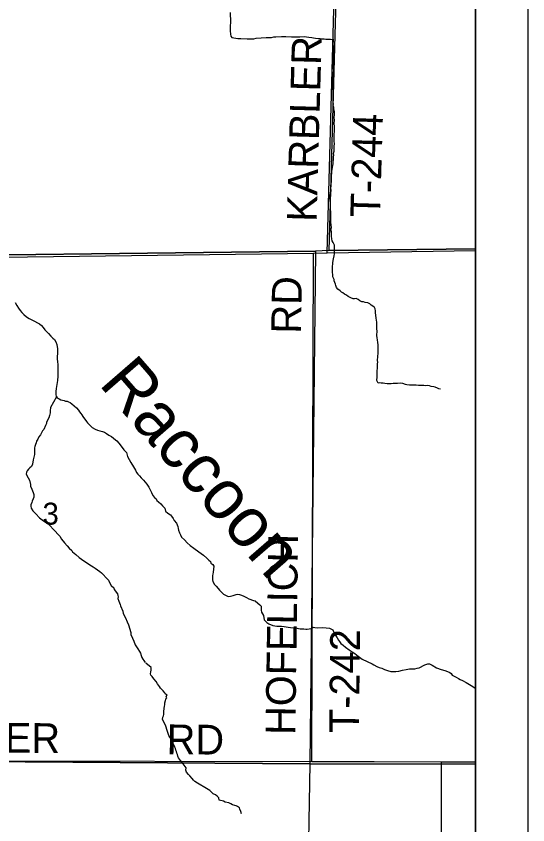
# Model space of a CAD drawing. Extents: x 0 to 34, y 0 to 22.
# Drawn here: x 29.44 to 30.417, y 18.79 to 20.335 of the extents above; entities that cross this region are included whole.
import ezdxf

# ---------------------------------------------------------------- set-up
doc = ezdxf.new("R2010")
doc.units = 0
for name, color, linetype in [('GM_X_County_Road', 7, 'Continuous'), ('GM_X_Minor_River', 7, 'Continuous'), ('GM_X_Minor_River_Text', 7, 'Continuous'), ('GM_X_Section', 7, 'Continuous'), ('GM_X_Section_Text', 7, 'Continuous'), ('GM_X_Township_Road', 7, 'Continuous'), ('GM_X_Township_Road_Text', 7, 'Continuous'), ('SH_Data', 7, 'Continuous')]:
    doc.layers.add(name, color=color, linetype=linetype)

msp = doc.modelspace()

# ---------------------------------------------------------------- linework, layer by layer
at = {"layer": 'GM_X_County_Road'}
msp.add_line((30.0335, 19.8831), (30.3167, 19.8876), dxfattribs=at)
msp.add_lwpolyline([(29.2621, 19.8726), (30.0076, 19.8826), (30.0335, 19.8831)], dxfattribs=at)
at = {"layer": 'GM_X_Minor_River'}
for points in [[(29.8485, 20.3425), (29.8486, 20.3235), (29.8482, 20.3163), (29.8483, 20.3072), (29.8491, 20.3007), (29.8494, 20.2973), (29.8517, 20.2946), (29.8631, 20.2924), (29.8688, 20.2925), (29.881, 20.2921), (29.8935, 20.2922), (29.8981, 20.2934), (29.9167, 20.2946), (29.922, 20.2942), (29.9273, 20.2943), (29.9318, 20.2954), (29.9356, 20.2958), (29.9466, 20.2962), (29.95, 20.2966), (29.9546, 20.2963), (29.9652, 20.2956), (29.9816, 20.2957), (29.9899, 20.2961), (29.9941, 20.2957), (29.9983, 20.295), (30.0043, 20.2942), (30.0074, 20.2935), (30.0112, 20.2931), (30.0165, 20.2928), (30.0199, 20.2924), (30.0237, 20.2917), (30.0275, 20.2917)], [(30.0275, 20.2917), (30.0309, 20.2913), (30.0355, 20.2913), (30.0397, 20.291), (30.0455, 20.2905)], [(30.0421, 19.91), (30.0418, 19.9149), (30.0415, 19.9195), (30.0415, 19.9229), (30.0408, 19.9278), (30.0416, 19.9312), (30.0405, 19.9415), (30.0406, 19.9563), (30.0403, 19.962), (30.04, 19.965), (30.0401, 19.9776), (30.0393, 19.9829), (30.0386, 19.9867), (30.039, 19.992), (30.0398, 19.9981), (30.041, 20.0015), (30.0407, 20.0072), (30.0411, 20.0098), (30.0411, 20.0151), (30.0415, 20.0186), (30.0416, 20.0269), (30.0425, 20.0383), (30.0437, 20.0459), (30.0445, 20.05), (30.0449, 20.0531), (30.0449, 20.0561), (30.0453, 20.0618), (30.0457, 20.0667), (30.0461, 20.0698), (30.0454, 20.0728), (30.0466, 20.0774), (30.047, 20.0827), (30.047, 20.0876), (30.0474, 20.0906), (30.0471, 20.0967), (30.0468, 20.1005), (30.0468, 20.1036), (30.0468, 20.1089), (30.0473, 20.1153), (30.0477, 20.1206), (30.0477, 20.1252), (30.047, 20.1298), (30.0475, 20.1366), (30.0471, 20.1415), (30.0475, 20.1465), (30.0472, 20.1491), (30.0472, 20.1529), (30.0465, 20.1579), (30.0461, 20.1609), (30.045, 20.1647), (30.0454, 20.1677), (30.0447, 20.1704), (30.0447, 20.1761), (30.0449, 20.1905), (30.0445, 20.1977), (30.0446, 20.2053), (30.0443, 20.2099), (30.0443, 20.2141), (30.0459, 20.2262), (30.046, 20.2319), (30.0456, 20.2349), (30.0457, 20.2422), (30.0453, 20.2478), (30.0454, 20.2516), (30.0458, 20.2554), (30.0451, 20.2604), (30.0455, 20.2634), (30.0459, 20.2672), (30.0459, 20.274), (30.0456, 20.2775), (30.0452, 20.2816), (30.0453, 20.2881), (30.0457, 20.2915)], [(30.2502, 19.6222), (30.2468, 19.6234), (30.2442, 19.6242), (30.24, 19.6261), (30.2374, 19.6269), (30.2321, 19.6277), (30.2287, 19.6289), (30.2249, 19.6297), (30.2218, 19.6286), (30.218, 19.6293), (30.212, 19.6294), (30.2082, 19.6298), (30.2036, 19.6302), (30.1961, 19.6299), (30.1907, 19.6303), (30.1858, 19.6311), (30.1832, 19.6315), (30.1783, 19.6331), (30.1726, 19.6339), (30.168, 19.6336), (30.1654, 19.6332), (30.1597, 19.6333), (30.1559, 19.6329), (30.1513, 19.6326), (30.1479, 19.633), (30.1434, 19.6334), (30.1403, 19.6338), (30.1365, 19.6342), (30.1339, 19.6343), (30.1312, 19.6339), (30.1294, 19.6366), (30.1282, 19.6392), (30.1287, 19.6461), (30.1288, 19.6548), (30.1296, 19.6654), (30.1296, 19.6707), (30.1301, 19.6738), (30.1297, 19.6772), (30.1305, 19.6848), (30.131, 19.6912), (30.131, 19.6947), (30.131, 19.6985), (30.1307, 19.7023), (30.1307, 19.7072), (30.13, 19.7114), (30.1293, 19.7167), (30.1289, 19.7205), (30.1286, 19.7251), (30.1287, 19.7342), (30.1283, 19.7372), (30.1284, 19.7505), (30.1273, 19.7581), (30.1266, 19.7642), (30.1255, 19.7684), (30.1256, 19.7725), (30.1252, 19.776), (30.1241, 19.7786), (30.1207, 19.7813), (30.1177, 19.7832), (30.1147, 19.7855), (30.1113, 19.7875), (30.106, 19.7883), (30.103, 19.7891), (30.0995, 19.7895), (30.0961, 19.7914), (30.0928, 19.7941), (30.089, 19.796), (30.0859, 19.7949), (30.0833, 19.7953), (30.0787, 19.7969), (30.0761, 19.798), (30.0735, 19.7996), (30.0701, 19.8023), (30.0667, 19.8038), (30.0637, 19.8065), (30.061, 19.8077), (30.0584, 19.8103), (30.0539, 19.8138), (30.0516, 19.8169), (30.0501, 19.8207), (30.0494, 19.8233), (30.0479, 19.8264), (30.0468, 19.8294), (30.0468, 19.8321), (30.0446, 19.837), (30.0442, 19.8416), (30.0439, 19.8454), (30.0439, 19.8507), (30.0436, 19.8572), (30.044, 19.8617), (30.0444, 19.8644), (30.0456, 19.8716), (30.0468, 19.8773), (30.0472, 19.8814), (30.0476, 19.8868), (30.0477, 19.8924), (30.0473, 19.8974), (30.0462, 19.9001), (30.0447, 19.9027), (30.0432, 19.9058), (30.0421, 19.91)], [(29.4379, 19.7878), (29.4406, 19.7825), (29.444, 19.7772), (29.4474, 19.7727), (29.4501, 19.7693), (29.4543, 19.7651), (29.4596, 19.7606), (29.4642, 19.7576), (29.4695, 19.7549), (29.4745, 19.7523), (29.4806, 19.7493), (29.484, 19.7474), (29.4878, 19.744), (29.4909, 19.7406), (29.4943, 19.736), (29.4974, 19.733), (29.5012, 19.7289), (29.5058, 19.7236), (29.5096, 19.7198), (29.5126, 19.7171), (29.5153, 19.713), (29.5172, 19.7077), (29.5176, 19.7035), (29.5188, 19.7001), (29.5188, 19.691), (29.5181, 19.6845), (29.5181, 19.6799), (29.5185, 19.6754), (29.5189, 19.6689), (29.5194, 19.6621), (29.5194, 19.6492), (29.5191, 19.6446), (29.5187, 19.6419), (29.5187, 19.6393), (29.518, 19.6351)], [(29.518, 19.6351), (29.5165, 19.6275), (29.5161, 19.6241), (29.5154, 19.618), (29.5154, 19.6119), (29.5158, 19.6093), (29.5177, 19.6059), (29.5216, 19.604), (29.525, 19.6021), (29.5311, 19.601), (29.5341, 19.5999), (29.5368, 19.5995), (29.5398, 19.5984), (29.5428, 19.5969), (29.5459, 19.5946), (29.5505, 19.5904), (29.5547, 19.587), (29.5589, 19.5821), (29.5608, 19.5795), (29.5631, 19.5761), (29.565, 19.5734), (29.5669, 19.5704), (29.5738, 19.5605), (29.5757, 19.5579), (29.5795, 19.5545), (29.5848, 19.5492), (29.5902, 19.5462), (29.5951, 19.5443), (29.5993, 19.5432), (29.6042, 19.5417), (29.6084, 19.5402), (29.6122, 19.5376), (29.6168, 19.5349), (29.6214, 19.5319), (29.629, 19.5259), (29.632, 19.5236), (29.6355, 19.5194), (29.6401, 19.5134), (29.6454, 19.5066), (29.65, 19.5016), (29.6519, 19.4941), (29.6588, 19.4827), (29.6634, 19.474), (29.6657, 19.471), (29.6672, 19.4675), (29.6695, 19.4634), (29.6722, 19.46), (29.6749, 19.4569), (29.6783, 19.4532), (29.6825, 19.4486), (29.686, 19.4448), (29.689, 19.4411), (29.6932, 19.435), (29.6978, 19.4251), (29.7005, 19.4195), (29.704, 19.4153), (29.707, 19.4127), (29.7082, 19.4096), (29.7112, 19.4074), (29.7158, 19.4032), (29.7192, 19.3998), (29.7234, 19.3949), (29.7246, 19.3892), (29.7292, 19.3854), (29.7341, 19.3824), (29.7364, 19.3797), (29.7391, 19.3756), (29.7414, 19.3718), (29.7456, 19.3665), (29.7486, 19.3604), (29.7487, 19.3566), (29.7498, 19.3528), (29.7517, 19.3479), (29.7533, 19.3441), (29.7556, 19.3399), (29.7609, 19.3347), (29.7663, 19.329), (29.7716, 19.3241), (29.7788, 19.3184), (29.7884, 19.312), (29.7975, 19.3052), (29.804, 19.2999), (29.8078, 19.2961), (29.8109, 19.2935), (29.8116, 19.2901), (29.8151, 19.2878), (29.817, 19.2844), (29.8166, 19.2783), (29.8159, 19.273), (29.8152, 19.2688), (29.8148, 19.2662), (29.8144, 19.2627), (29.8144, 19.2582), (29.8152, 19.2551), (29.8183, 19.2495), (29.8213, 19.2461), (29.8252, 19.2415), (29.8278, 19.2385), (29.8313, 19.2351), (29.8358, 19.2309), (29.8393, 19.2287)], [(29.5167, 19.6077), (29.5054, 19.5876), (29.5048, 19.5812), (29.5044, 19.5774), (29.5036, 19.5748), (29.5035, 19.5721), (29.5019, 19.568), (29.4976, 19.5597), (29.4972, 19.5571), (29.4956, 19.5533), (29.4924, 19.5454), (29.49, 19.5428), (29.4861, 19.5353), (29.483, 19.5316), (29.481, 19.5271), (29.4787, 19.5233), (29.4778, 19.5199), (29.4763, 19.5169), (29.475, 19.5131), (29.4746, 19.5105), (29.4745, 19.504), (29.4748, 19.5002), (29.4743, 19.4976), (29.4735, 19.4927), (29.4722, 19.4874), (29.4709, 19.4791), (29.4689, 19.4749), (29.4659, 19.472), (29.4631, 19.4694), (29.4608, 19.4664), (29.4592, 19.4638), (29.4588, 19.4604), (29.4628, 19.4531), (29.465, 19.4485), (29.4671, 19.4401), (29.467, 19.4374), (29.4695, 19.4313), (29.4721, 19.4248), (29.4731, 19.421), (29.4734, 19.4164), (29.4722, 19.4127), (29.4702, 19.4085), (29.4694, 19.4059), (29.4678, 19.4018), (29.4674, 19.3991), (29.468, 19.3953), (29.4717, 19.3903), (29.4769, 19.3841), (29.4839, 19.3768), (29.4918, 19.3709), (29.5007, 19.3654), (29.5141, 19.3515), (29.5192, 19.3453), (29.5237, 19.3411), (29.5255, 19.3365), (29.5296, 19.3322), (29.5318, 19.3288), (29.5373, 19.323), (29.5406, 19.3187), (29.5458, 19.3141), (29.5473, 19.3114), (29.5533, 19.3064), (29.56, 19.3009), (29.5689, 19.2943), (29.576, 19.29), (29.5805, 19.2868), (29.5835, 19.2849), (29.5868, 19.2829), (29.5906, 19.2802), (29.5951, 19.2774), (29.5992, 19.2743), (29.6025, 19.2716), (29.6058, 19.2681), (29.6114, 19.2619), (29.6158, 19.2573), (29.6169, 19.2543), (29.6213, 19.2473), (29.6258, 19.2427), (29.6265, 19.24), (29.6331, 19.2312), (29.6338, 19.2285), (29.6341, 19.2258), (29.634, 19.2228), (29.6358, 19.2175), (29.6384, 19.2113), (29.6387, 19.2087), (29.6434, 19.1983), (29.6437, 19.1938), (29.6484, 19.1853), (29.6517, 19.1777), (29.6538, 19.1723), (29.6584, 19.1575), (29.6587, 19.154), (29.662, 19.1468), (29.6641, 19.141), (29.667, 19.1341), (29.6692, 19.1303), (29.6722, 19.1261), (29.6751, 19.1211), (29.6773, 19.118), (29.678, 19.1138)], [(29.8393, 19.2287), (29.8431, 19.2272), (29.8457, 19.2264), (29.8488, 19.2268), (29.8541, 19.2284), (29.8598, 19.2303), (29.8632, 19.2307), (29.8658, 19.2299), (29.87, 19.2288), (29.8746, 19.2269), (29.8795, 19.2243), (29.8837, 19.222), (29.8928, 19.2187), (29.8963, 19.2179), (29.9012, 19.2138), (29.905, 19.2104), (29.9073, 19.2077), (29.9077, 19.2001), (29.9078, 19.1963), (29.912, 19.1899), (29.9135, 19.1819), (29.9181, 19.1766), (29.9223, 19.174), (29.9295, 19.171), (29.9371, 19.1695), (29.9462, 19.1695), (29.9512, 19.1692), (29.955, 19.1681), (29.9588, 19.1677), (29.9633, 19.1673), (29.969, 19.1666), (29.9724, 19.1662), (29.9762, 19.1659), (29.9789, 19.1651), (29.9819, 19.1648), (29.9857, 19.1648), (29.9892, 19.1644), (29.9926, 19.1637), (29.9952, 19.1637), (29.999, 19.1645), (30.0021, 19.1653), (30.0047, 19.166)], [(30.0042, 19.1659), (30.007, 19.1679), (30.01, 19.1672), (30.0142, 19.1668), (30.0244, 19.1669), (30.0313, 19.1665), (30.0377, 19.1658), (30.0442, 19.1624), (30.0473, 19.1548), (30.0526, 19.1473), (30.0553, 19.1427), (30.0568, 19.1401), (30.0599, 19.1367), (30.0641, 19.1333), (30.0687, 19.1295), (30.0755, 19.1242), (30.0812, 19.1208), (30.0866, 19.1174), (30.093, 19.1125), (30.1003, 19.1068), (30.1193, 19.0974), (30.1224, 19.0956), (30.1281, 19.0929), (30.133, 19.091), (30.1376, 19.0892), (30.1429, 19.0869), (30.149, 19.0847), (30.1551, 19.0828), (30.16, 19.0828), (30.1646, 19.0832), (30.1702, 19.084), (30.1774, 19.0859), (30.1843, 19.0871), (30.1907, 19.0879), (30.196, 19.0883), (30.201, 19.0883), (30.2051, 19.0895), (30.2089, 19.0903), (30.2203, 19.096), (30.2256, 19.0979), (30.2286, 19.098), (30.2343, 19.0953), (30.2423, 19.0901), (30.2511, 19.0871), (30.2537, 19.0863), (30.2598, 19.0844), (30.2678, 19.0811), (30.2705, 19.0792), (30.272, 19.0761), (30.2796, 19.0724), (30.2842, 19.0697), (30.2876, 19.0679), (30.2918, 19.066), (30.2987, 19.0622), (30.3086, 19.0562), (30.3158, 19.052), (30.3167, 19.0512)], [(29.678, 19.1138), (29.6798, 19.1096), (29.6812, 19.1069), (29.6834, 19.1038), (29.686, 19.1)], [(29.8699, 18.8112), (29.8684, 18.8158), (29.8669, 18.8199), (29.8658, 18.8226), (29.8624, 18.8249), (29.8598, 18.8261), (29.8571, 18.8269), (29.853, 18.8284), (29.8496, 18.8304), (29.8454, 18.8319), (29.839, 18.8335), (29.8356, 18.835), (29.8272, 18.837), (29.8265, 18.8419), (29.8235, 18.845), (29.8205, 18.8473), (29.8156, 18.8496), (29.813, 18.8519), (29.8092, 18.8554), (29.8028, 18.8592), (29.7858, 18.8696), (29.7809, 18.8727), (29.7783, 18.8754), (29.776, 18.8788), (29.7711, 18.8834), (29.7685, 18.8861), (29.7651, 18.8907), (29.7636, 18.8945), (29.7641, 18.8991), (29.7622, 18.9017), (29.7588, 18.9067), (29.7536, 18.9132), (29.7498, 18.9178), (29.7483, 18.9212), (29.7476, 18.9243), (29.7461, 18.9269), (29.7457, 18.93), (29.7446, 18.933), (29.7439, 18.9357), (29.7428, 18.9384), (29.7413, 18.9418), (29.7383, 18.9479), (29.7349, 18.954), (29.7331, 18.9578), (29.7312, 18.9609), (29.7297, 18.9643), (29.7282, 18.9704), (29.7253, 18.9784), (29.7216, 18.9868), (29.7189, 18.9913), (29.7194, 18.9959), (29.7209, 18.9985), (29.7213, 19.0012), (29.7217, 19.0069), (29.7221, 19.0122), (29.7226, 19.0167), (29.7233, 19.0194), (29.7234, 19.0232), (29.7245, 19.0274), (29.7257, 19.03), (29.7272, 19.0327), (29.7261, 19.0353), (29.7277, 19.038), (29.7246, 19.0395), (29.7235, 19.0422), (29.7205, 19.046), (29.7175, 19.0487), (29.7149, 19.0514), (29.7134, 19.0544), (29.7093, 19.0598), (29.7067, 19.064), (29.7025, 19.0689), (29.6991, 19.0735), (29.6969, 19.0762), (29.6962, 19.0789), (29.6969, 19.0823), (29.6973, 19.0853), (29.6977, 19.088), (29.6974, 19.0906), (29.6873, 19.0991)]]:
    msp.add_lwpolyline(points, dxfattribs=at)
at = {"layer": 'GM_X_Section'}
for points in [[(30.0649, 20.8926), (30.0369, 19.8872), (30.0112, 19.8862), (29.0488, 19.8748), (29.0645, 20.8822)], [(30.3167, 19.8909), (30.3167, 20.8955), (30.0649, 20.8926), (30.0369, 19.8872)], [(30.0112, 19.8862), (30.0004, 18.9065), (29.0034, 18.9139), (29.0105, 19.8743), (29.0488, 19.8748)], [(30.3167, 18.9058), (30.3167, 19.8909), (30.0369, 19.8872), (30.0112, 19.8862), (30.0004, 18.9065)]]:
    msp.add_lwpolyline(points, close=True, dxfattribs=at)
for points in [[(28.9945, 18.1387), (29.0034, 18.9139), (30.0004, 18.9065), (29.9873, 18.1387)], [(29.9962, 17.9263), (30.3167, 17.9232), (30.3167, 18.9058), (30.0004, 18.9065), (29.9873, 18.1387)]]:
    msp.add_lwpolyline(points, dxfattribs=at)
at = {"layer": 'GM_X_Township_Road'}
for p, q in [((30.0335, 19.8831), (30.0474, 20.3884)), ((30.0045, 18.9111), (30.0076, 19.8826)), ((29.3398, 18.9126), (30.0045, 18.9111)), ((30.2519, 18.9106), (30.3167, 18.9104))]:
    msp.add_line(p, q, dxfattribs=at)
for points in [[(30.0045, 18.9111), (30.1233, 18.9109), (30.2519, 18.9106)], [(30.2501, 18.3387), (30.2517, 18.4916), (30.2517, 18.7656), (30.2519, 18.9106)]]:
    msp.add_lwpolyline(points, dxfattribs=at)
at = {"layer": 'SH_Data'}
for points in [[(23.4167, 21), (30.4167, 21), (30.4167, 14), (23.4167, 14)], [(23.5167, 20.9), (30.3167, 20.9), (30.3167, 14.1), (23.5167, 14.1)]]:
    msp.add_lwpolyline(points, close=True, dxfattribs=at)

# ---------------------------------------------------------------- texts
at = {"layer": 'GM_X_Minor_River_Text'}
msp.add_text('Raccoon', height=0.09475, rotation=310.9846, dxfattribs=at).set_placement((29.5957, 19.632))
at = {"layer": 'GM_X_Section_Text'}
msp.add_text('3', height=0.0419, rotation=0, dxfattribs=at).set_placement((29.4899, 19.3637))
at = {"layer": 'GM_X_Township_Road_Text'}
for s, rotation, p in [('KARBLER', 88.3806, (30.0132, 19.9417)), ('T-244', 88.3152, (30.1343, 19.9499)), ('RD', 89.0128, (29.9834, 19.7282)), ('HOFELICH', 89.1656, (29.9725, 18.9615)), ('T-242', 89.4386, (30.0943, 18.9652)), ('BOOKMEYER', 359.4573, (29.0335, 18.9318)), ('RD', 359.5063, (29.7267, 18.9251))]:
    msp.add_text(s, height=0.05682, rotation=rotation, dxfattribs=at).set_placement(p)

doc.saveas('drawing.dxf')
